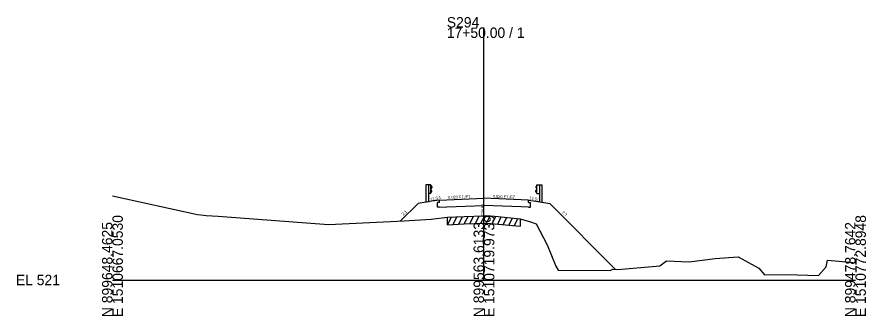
# Model space of a CAD drawing. Extents: x 974 to 2203, y -10 to 19041.
# Drawn here: x 974.3 to 1202.8, y 14990.3 to 15070.8 of the extents above; entities that cross this region are included whole.
import ezdxf

# ---------------------------------------------------------------- set-up
doc = ezdxf.new("R2010")
doc.units = 0
for name, color, linetype in [('RD_GPK_XS_Cell', 7, 'Continuous'), ('RD_XS_Base', 7, 'Continuous'), ('RD_XS_EarthShd', 7, 'Continuous'), ('RD_XS_ExGround', 7, 'Continuous'), ('RD_XS_ExPaveRet', 7, 'Continuous'), ('RD_XS_GR', 7, 'Continuous'), ('RD_XS_Pave', 7, 'Continuous'), ('RD_XS_TX_Elev_EX', 7, 'Continuous'), ('RD_XS_TX_Slope', 7, 'Continuous')]:
    doc.layers.add(name, color=color, linetype=linetype)

msp = doc.modelspace()

# ---------------------------------------------------------------- linework, layer by layer
at = {"layer": 'RD_GPK_XS_Cell'}
for p, q in [((1100, 15000), (1100, 15067.96)), ((1000, 15000), (1100, 15000)), ((1100, 15000), (1200, 15000))]:
    msp.add_line(p, q, dxfattribs=at)
at = {"layer": 'RD_XS_Base'}
for p, q in [((1088, 15020.88), (1088, 15021.52)), ((1112, 15020.88), (1112, 15021.52)), ((1088, 15020.88), (1087.5, 15020.86)), ((1087.5, 15019.59), (1087.5, 15020.86)), ((1088, 15019.61), (1087.5, 15019.59)), ((1088, 15019.61), (1090, 15019.69)), ((1090, 15019.69), (1100, 15020.09)), ((1110, 15019.69), (1100, 15020.09)), ((1112, 15019.61), (1110, 15019.69)), ((1112, 15020.88), (1112.5, 15020.86)), ((1112, 15019.61), (1112.5, 15019.59)), ((1112.5, 15019.59), (1112.5, 15020.86))]:
    msp.add_line(p, q, dxfattribs=at)
at = {"layer": 'RD_XS_EarthShd'}
for p, q in [((1088, 15021.52), (1086, 15021.19)), ((1112, 15021.52), (1114, 15021.19)), ((1077.58, 15015.9), (1082.25, 15020.56)), ((1086, 15021.19), (1082.25, 15020.56)), ((1114, 15021.19), (1117.75, 15020.56)), ((1135.45, 15002.87), (1117.75, 15020.56))]:
    msp.add_line(p, q, dxfattribs=at)
at = {"layer": 'RD_XS_ExGround'}
msp.add_lwpolyline([(1000, 15022.65), (1022.91, 15017.62), (1024.62, 15017.44), (1025.21, 15017.4), (1028.42, 15017.2), (1058.16, 15014.9), (1078.54, 15015.96), (1085.79, 15016.42), (1090.2, 15016.88), (1094.67, 15017.09), (1100, 15017.3), (1100.76, 15017.33), (1103.79, 15017.05), (1109.74, 15016.49), (1112.53, 15015.66), (1114.05, 15015.09), (1117, 15009.5), (1119.38, 15003.72), (1120.02, 15002.67), (1134.01, 15002.56), (1134.65, 15002.88), (1136.05, 15002.85), (1147.33, 15003.83), (1149.14, 15005.17), (1155.27, 15004.85), (1162.2, 15005.77), (1168.46, 15006.28), (1174.01, 15003.18), (1175.5, 15001.42), (1181.48, 15001.52), (1190.04, 15001.18), (1192.14, 15003.53), (1192.44, 15005.35), (1198.55, 15004.81), (1200, 15004.66)], dxfattribs=at)
at = {"layer": 'RD_XS_ExPaveRet'}
for p, q in [((1090.2, 15014.88), (1091.23, 15016.93)), ((1090.2, 15014.88), (1090.2, 15016.88)), ((1091.7, 15014.95), (1092.73, 15017)), ((1093.2, 15015.02), (1094.23, 15017.07)), ((1094.7, 15015.09), (1095.72, 15017.13)), ((1096.2, 15015.15), (1097.22, 15017.19)), ((1097.7, 15015.21), (1098.72, 15017.25)), ((1099.2, 15015.27), (1100.22, 15017.31)), ((1100.7, 15015.32), (1101.66, 15017.25)), ((1102.2, 15015.2), (1103.16, 15017.11)), ((1103.7, 15015.06), (1104.66, 15016.97)), ((1090.2, 15014.88), (1094.67, 15015.09)), ((1094.67, 15015.09), (1100, 15015.3)), ((1100, 15015.3), (1100.76, 15015.33)), ((1100.76, 15015.33), (1103.79, 15015.05)), ((1103.79, 15015.05), (1109.74, 15014.49)), ((1105.2, 15014.92), (1106.16, 15016.83)), ((1106.7, 15014.78), (1107.66, 15016.68)), ((1108.2, 15014.63), (1109.16, 15016.54)), ((1109.74, 15016.49), (1109.74, 15014.49))]:
    msp.add_line(p, q, dxfattribs=at)
at = {"layer": 'RD_XS_GR'}
for p, q in [((1084.4, 15025.6), (1084.4, 15020.84)), ((1085.06, 15025.6), (1084.4, 15025.6)), ((1085.06, 15025.6), (1085.06, 15020.95)), ((1085.73, 15025.6), (1085.06, 15025.6)), ((1085.73, 15023.27), (1085.73, 15025.6)), ((1085.73, 15025.46), (1086, 15025.06)), ((1086, 15024.96), (1085.73, 15024.56)), ((1086, 15023.92), (1085.73, 15024.32)), ((1085.73, 15023.42), (1086, 15023.82)), ((1086, 15025.06), (1086, 15024.96)), ((1086, 15023.82), (1086, 15023.92)), ((1114.27, 15025.46), (1114, 15025.06)), ((1114, 15025.06), (1114, 15024.96)), ((1114, 15024.96), (1114.27, 15024.56)), ((1114, 15023.92), (1114.27, 15024.32)), ((1114, 15023.82), (1114, 15023.92)), ((1114.27, 15023.42), (1114, 15023.82)), ((1114.27, 15025.6), (1114.94, 15025.6)), ((1114.27, 15023.27), (1114.27, 15025.6)), ((1114.94, 15025.6), (1114.94, 15020.95)), ((1114.94, 15025.6), (1115.6, 15025.6)), ((1115.6, 15025.6), (1115.6, 15020.84)), ((1085.73, 15023.27), (1085.06, 15023.27)), ((1114.27, 15023.27), (1114.94, 15023.27))]:
    msp.add_line(p, q, dxfattribs=at)
at = {"layer": 'RD_XS_Pave'}
for p, q in [((1088, 15021.52), (1090, 15021.6)), ((1090, 15021.6), (1100, 15022)), ((1110, 15021.6), (1100, 15022)), ((1112, 15021.52), (1110, 15021.6))]:
    msp.add_line(p, q, dxfattribs=at)

# ---------------------------------------------------------------- texts
at = {"layer": 'RD_GPK_XS_Cell'}
for s, p in [('S294', (1090, 15067.96)), ('17+50.00 / 1', (1090, 15065.16)), ('EL 521', (974, 14998.6))]:
    msp.add_text(s, height=2.8, dxfattribs=at).set_placement(p)
for s, p in [('E 1510667.0530', (1002.8, 14990)), ('E 1510719.9739', (1102.8, 14990)), ('E 1510772.8948', (1202.8, 14990)), ('N 899648.4625', (1000, 14990)), ('N 899563.6133', (1100, 14990)), ('N 899478.7642', (1200, 14990))]:
    msp.add_text(s, height=2.8, rotation=90, dxfattribs=at).set_placement(p)
at = {"layer": 'RD_XS_TX_Elev_EX'}
msp.add_text('529.65', height=0.75, rotation=90, dxfattribs=at).set_placement((1100, 15017.3))
at = {"layer": 'RD_XS_TX_Slope'}
for s, height, rotation, p in [('12.5:1', 0.778, 12.7511, (1085.61, 15021.26)), ('0.020 FT./FT.', 0.7518, 2.2327, (1090.38, 15021.85)), ('0.020 FT./FT.', 0.7518, 357.7673, (1102.39, 15022.14)), ('12.5:1', 0.778, 347.2489, (1112.17, 15021.77)), ('2:1', 0.778, 40.6589, (1078.23, 15017.28)), ('2:1', 0.778, 319.3411, (1120.92, 15018.02))]:
    msp.add_text(s, height=height, rotation=rotation, dxfattribs=at).set_placement(p)

doc.saveas('drawing.dxf')
